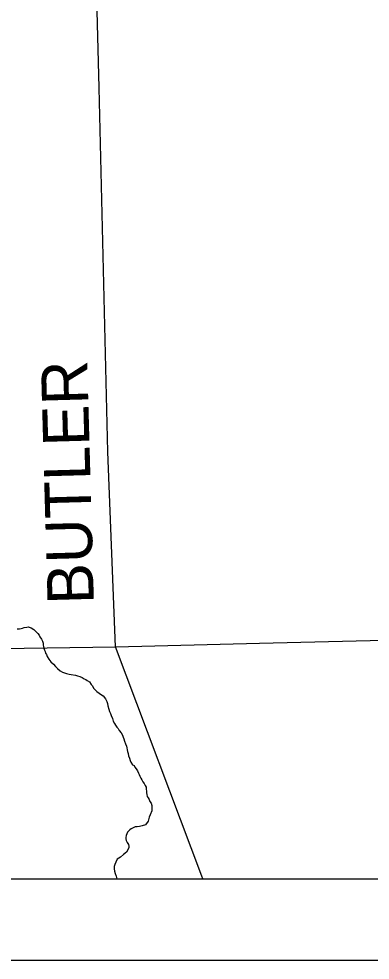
# Model space of a CAD drawing. Extents: x 0 to 34, y 0 to 22.
# Drawn here: x 5.957 to 6.388, y 14 to 15.155 of the extents above; entities that cross this region are included whole.
import ezdxf

# ---------------------------------------------------------------- set-up
doc = ezdxf.new("R2010")
doc.units = 0
for name, color, linetype in [('GM_X_Corporation', 7, 'Continuous'), ('GM_X_County_Road', 7, 'Continuous'), ('GM_X_County_Road_Text', 7, 'Continuous'), ('GM_X_Minor_River', 7, 'Continuous'), ('SH_Data', 7, 'Continuous')]:
    doc.layers.add(name, color=color, linetype=linetype)

msp = doc.modelspace()

# ---------------------------------------------------------------- linework, layer by layer
at = {"layer": 'GM_X_Corporation'}
msp.add_lwpolyline([(2.1, 20.3879), (2.1, 14.1), (7.1335, 14.1), (7.1269, 14.4049), (7.1267, 14.4123), (7.1215, 14.6514), (7.118, 14.8105), (7.1072, 15.3824), (7.0838, 16.6084)], dxfattribs=at)
msp.add_lwpolyline([(2.1, 15.3574), (2.1, 14.1), (7.1335, 14.1), (7.1269, 14.4049), (7.1267, 14.4123), (7.1215, 14.6514), (7.118, 14.8105), (7.1072, 15.3824), (6.0415, 15.3685), (5.8313, 15.3671), (5.1944, 15.3696), (4.1554, 15.3654), (4.1534, 15.3654), (3.4135, 15.3624), (2.6127, 15.3592)], close=True, dxfattribs=at)
at = {"layer": 'GM_X_County_Road'}
for points in [[(6.1825, 14.1), (6.1814, 14.103), (6.0754, 14.3845), (6.0658, 14.624), (6.0555, 15.0705), (6.0505, 15.2593), (6.0489, 15.2901), (6.0444, 15.3349), (6.0417, 15.3679)], [(6.0754, 14.3845), (6.2518, 14.3889), (6.608, 14.3975), (7.1269, 14.4117)], [(3.4637, 14.2828), (3.4705, 14.2865), (3.4834, 14.2899), (3.5484, 14.2951), (3.6062, 14.2988), (3.6339, 14.2982), (3.6511, 14.2957), (3.6628, 14.292), (3.6812, 14.2847), (3.6986, 14.2775), (3.7141, 14.2746), (3.7758, 14.2933), (3.8973, 14.3317), (3.9354, 14.344), (3.9526, 14.3483), (3.9767, 14.3512), (4.4934, 14.358), (4.9174, 14.3648), (5.3258, 14.3705), (5.4131, 14.3722), (5.5063, 14.374), (5.7673, 14.3801), (6.0754, 14.3845)]]:
    msp.add_lwpolyline(points, dxfattribs=at)
at = {"layer": 'GM_X_Minor_River'}
for points in [[(5.9547, 14.4067), (5.9577, 14.4066), (5.9596, 14.407), (5.9615, 14.4074), (5.9634, 14.4081), (5.9665, 14.4085), (5.9684, 14.4089), (5.9718, 14.4077), (5.9752, 14.4058), (5.9787, 14.4027), (5.9802, 14.4008), (5.9817, 14.3989), (5.9828, 14.3966), (5.9847, 14.3939), (5.9858, 14.3916), (5.9866, 14.389), (5.9869, 14.3867), (5.9873, 14.3848), (5.9877, 14.3829), (5.9884, 14.3806), (5.9892, 14.3787), (5.9896, 14.3768), (5.9907, 14.3749), (5.9918, 14.3726), (5.9937, 14.3695), (5.996, 14.3661), (5.9994, 14.3634), (6.0017, 14.3603), (6.0043, 14.358), (6.0077, 14.355), (6.0104, 14.3534), (6.0127, 14.3527), (6.0153, 14.3519)], [(6.0153, 14.3519), (6.0184, 14.3511), (6.021, 14.3507), (6.0264, 14.3499), (6.029, 14.3491), (6.0317, 14.3483), (6.0344, 14.3468), (6.037, 14.3453), (6.0389, 14.3445), (6.0408, 14.3433), (6.0435, 14.3414), (6.0457, 14.3384), (6.0473, 14.3365), (6.0484, 14.3338), (6.0503, 14.3319), (6.0525, 14.3296), (6.0552, 14.3277), (6.0571, 14.3265), (6.0601, 14.3242), (6.0632, 14.3208), (6.0647, 14.3173), (6.0654, 14.315), (6.0662, 14.312), (6.0673, 14.3082), (6.068, 14.3051), (6.0692, 14.3025), (6.0699, 14.3002), (6.0718, 14.2964), (6.0725, 14.2933), (6.0741, 14.2906), (6.0756, 14.2884), (6.0771, 14.2861), (6.0786, 14.2841), (6.0801, 14.2819), (6.0824, 14.2788), (6.0839, 14.2761), (6.0846, 14.2738), (6.0858, 14.2716), (6.0865, 14.2689), (6.0876, 14.2655), (6.0888, 14.2628), (6.0903, 14.2559), (6.091, 14.2536), (6.0914, 14.2506), (6.0925, 14.2479), (6.0932, 14.2449), (6.0944, 14.243), (6.0963, 14.2399), (6.0982, 14.2388), (6.0993, 14.2369), (6.1008, 14.2346), (6.1023, 14.2323), (6.1038, 14.2296), (6.1046, 14.2277), (6.1053, 14.2258), (6.1065, 14.2235), (6.1076, 14.2212), (6.1091, 14.2189), (6.1106, 14.2166), (6.1117, 14.2143), (6.1129, 14.2121), (6.1132, 14.2101), (6.1136, 14.2071), (6.1136, 14.2052), (6.114, 14.2033), (6.1143, 14.201), (6.1155, 14.1991), (6.1166, 14.1972), (6.1177, 14.1949), (6.1193, 14.1926), (6.12, 14.19), (6.12, 14.1831), (6.118, 14.1782), (6.1165, 14.1755), (6.1153, 14.1706), (6.1123, 14.166), (6.1081, 14.1649), (6.105, 14.1642), (6.102, 14.1638), (6.0997, 14.1635), (6.097, 14.1624), (6.0947, 14.1612), (6.0928, 14.1601), (6.0901, 14.1571), (6.0893, 14.1552), (6.0886, 14.1529), (6.0882, 14.1506), (6.0882, 14.1487), (6.0885, 14.1468), (6.0897, 14.1445), (6.0912, 14.1419), (6.0919, 14.14), (6.0919, 14.1377), (6.0888, 14.1324), (6.0854, 14.1297), (6.0816, 14.1263), (6.0774, 14.1241), (6.0758, 14.1203), (6.0747, 14.1173), (6.0739, 14.115), (6.0739, 14.1119)], [(6.0739, 14.1119), (6.0742, 14.1093), (6.075, 14.1062), (6.0761, 14.1032), (6.0771, 14.1)]]:
    msp.add_lwpolyline(points, dxfattribs=at)
at = {"layer": 'SH_Data'}
for p, q in [((2.1, 14.1), (8.9, 14.1)), ((2, 14), (9, 14))]:
    msp.add_line(p, q, dxfattribs=at)

# ---------------------------------------------------------------- texts
at = {"layer": 'GM_X_County_Road_Text'}
msp.add_text('BUTLER', height=0.05682, rotation=91.5918, dxfattribs=at).set_placement((6.049, 14.4372))

doc.saveas('drawing.dxf')
